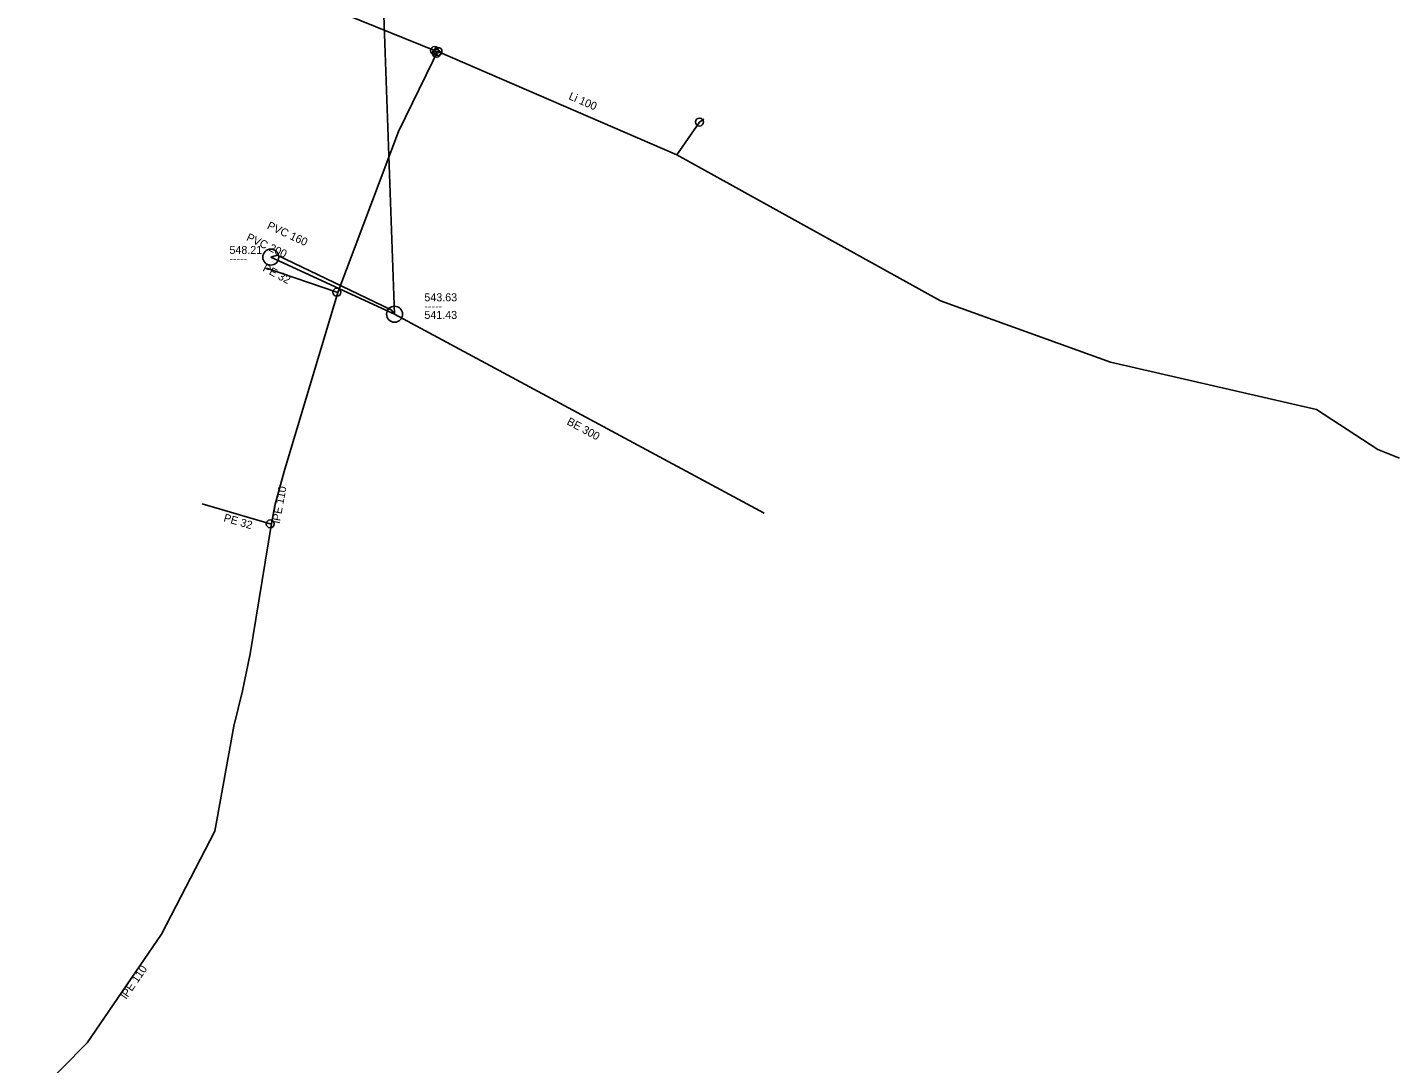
# Model space of a CAD drawing. Extents: x -701133 to -700495, y -1142806 to -1142020.
# Drawn here: x -700666.6 to -700495.1, y -1142398.7 to -1142269.2 of the extents above; entities that cross this region are included whole.
import ezdxf

# ---------------------------------------------------------------- set-up
doc = ezdxf.new("R2010")
doc.units = 0
doc.layers.add('Level 0', color=7, linetype='Continuous')

msp = doc.modelspace()

# ---------------------------------------------------------------- linework, layer by layer
at = {"layer": 'Level 0'}
for p, q in [((-700623.12, -1142236.71), (-700620.7, -1142305.05)), ((-700634.65, -1142264.41), (-700615.7, -1142272.11)), ((-700615.89, -1142273.33), (-700620.21, -1142282.23)), ((-700615.46, -1142272.43), (-700615.89, -1142273.33)), ((-700615.54, -1142272.17), (-700615.7, -1142272.11)), ((-700615.27, -1142272.2), (-700615.54, -1142272.17)), ((-700615.54, -1142272.17), (-700615.46, -1142272.43)), ((-700615.27, -1142272.2), (-700585.43, -1142285.14)), ((-700585.43, -1142285.14), (-700582.6, -1142281.04)), ((-700582.6, -1142281.04), (-700582.06, -1142280.69)), ((-700620.21, -1142282.23), (-700627.77, -1142302.35)), ((-700585.43, -1142285.14), (-700552.46, -1142303.36)), ((-700627.91, -1142302.3), (-700636.68, -1142299.3)), ((-700636.17, -1142297.92), (-700635.36, -1142297.67)), ((-700636.17, -1142297.92), (-700620.7, -1142305.05)), ((-700635.36, -1142297.67), (-700621.12, -1142304.49)), ((-700627.77, -1142302.35), (-700634.49, -1142324.69)), ((-700627.77, -1142302.35), (-700627.91, -1142302.3)), ((-700552.46, -1142303.36), (-700531.24, -1142311.03)), ((-700621.12, -1142304.49), (-700620.7, -1142305.05)), ((-700620.7, -1142305.05), (-700574.51, -1142329.91)), ((-700531.24, -1142311.03), (-700505.48, -1142316.95)), ((-700505.48, -1142316.95), (-700497.82, -1142321.95)), ((-700497.82, -1142321.95), (-700495.12, -1142323.04)), ((-700634.49, -1142324.69), (-700635.64, -1142328.96)), ((-700636.24, -1142331.25), (-700644.73, -1142328.77)), ((-700635.64, -1142328.96), (-700636.06, -1142331.21)), ((-700636.06, -1142331.21), (-700638.03, -1142343.16)), ((-700636.06, -1142331.21), (-700636.24, -1142331.25)), ((-700638.03, -1142343.17), (-700638.76, -1142347.5)), ((-700638.03, -1142343.16), (-700638.03, -1142343.17)), ((-700638.76, -1142347.5), (-700639.71, -1142352.14)), ((-700639.71, -1142352.14), (-700640.76, -1142356.55)), ((-700640.76, -1142356.55), (-700643.16, -1142369.67)), ((-700643.16, -1142369.67), (-700649.83, -1142382.55)), ((-700649.83, -1142382.55), (-700659.1, -1142396.13)), ((-700659.1, -1142396.13), (-700666.57, -1142403.66))]:
    msp.add_line(p, q, dxfattribs=at)
for centre, radius in [((-700615.7, -1142272.11), 0.5), ((-700615.27, -1142272.2), 0.5), ((-700615.46, -1142272.43), 0.5), ((-700582.6, -1142281.04), 0.5), ((-700636.17, -1142297.92), 1), ((-700627.91, -1142302.3), 0.5), ((-700620.7, -1142305.05), 1), ((-700636.24, -1142331.25), 0.5)]:
    msp.add_circle(centre, radius, dxfattribs=at)

# ---------------------------------------------------------------- texts
for s, rotation, p in [('Li 100', 336.556, (-700599.03, -1142278.15)), ('PVC 160', 335.255, (-700636.71, -1142294.32)), ('PVC 200', 335.092, (-700639.3, -1142295.79)), ('PE 32', 332.065, (-700637.26, -1142299.6)), ('BE 300', 331.71, (-700599.26, -1142318.77)), ('lPE 110', 79.426, (-700635.05, -1142331.25)), ('PE 32', 343.716, (-700642.13, -1142330.91)), ('lPE 110', 55.682, (-700654.2, -1142390.73))]:
    msp.add_text(s, height=1, rotation=rotation, dxfattribs=at).set_placement(p)
for s, p in [('548.21', (-700641.33, -1142297.52)), ('-----', (-700641.33, -1142298.62)), ('543.63', (-700616.97, -1142303.44)), ('-----', (-700616.97, -1142304.54)), ('541.43', (-700616.97, -1142305.64))]:
    msp.add_text(s, height=1, dxfattribs=at).set_placement(p)

doc.saveas('drawing.dxf')
